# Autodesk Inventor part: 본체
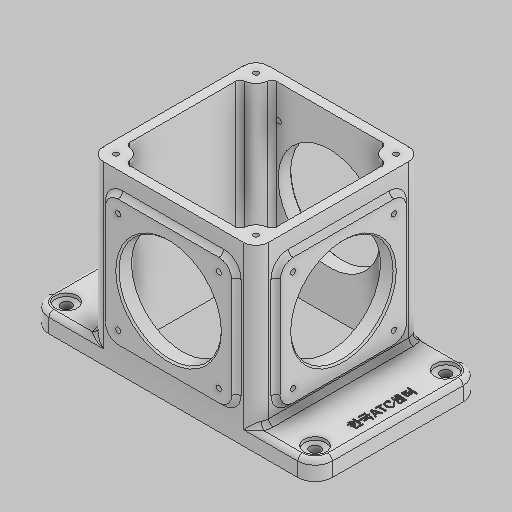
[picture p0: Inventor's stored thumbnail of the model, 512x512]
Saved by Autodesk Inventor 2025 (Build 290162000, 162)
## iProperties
Created: 2024-08
Part Number: 본체
Material: 알루미늄 6061
Document SubType Name: Modeling
Designer: 현기
Density: 2.7 g/cm^3
Appearance: 알루미늄 - 평지
Mass: 969.416 g
Surface Area: 957.183 cm^2
Volume: 359.043 cm^3
Sending System: Autodesk Inventor 2025
Preprocessor: ST-DEVELOPER v20
Author: jhkim
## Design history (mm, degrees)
feature "솔리드1"
node "솔리드2"
